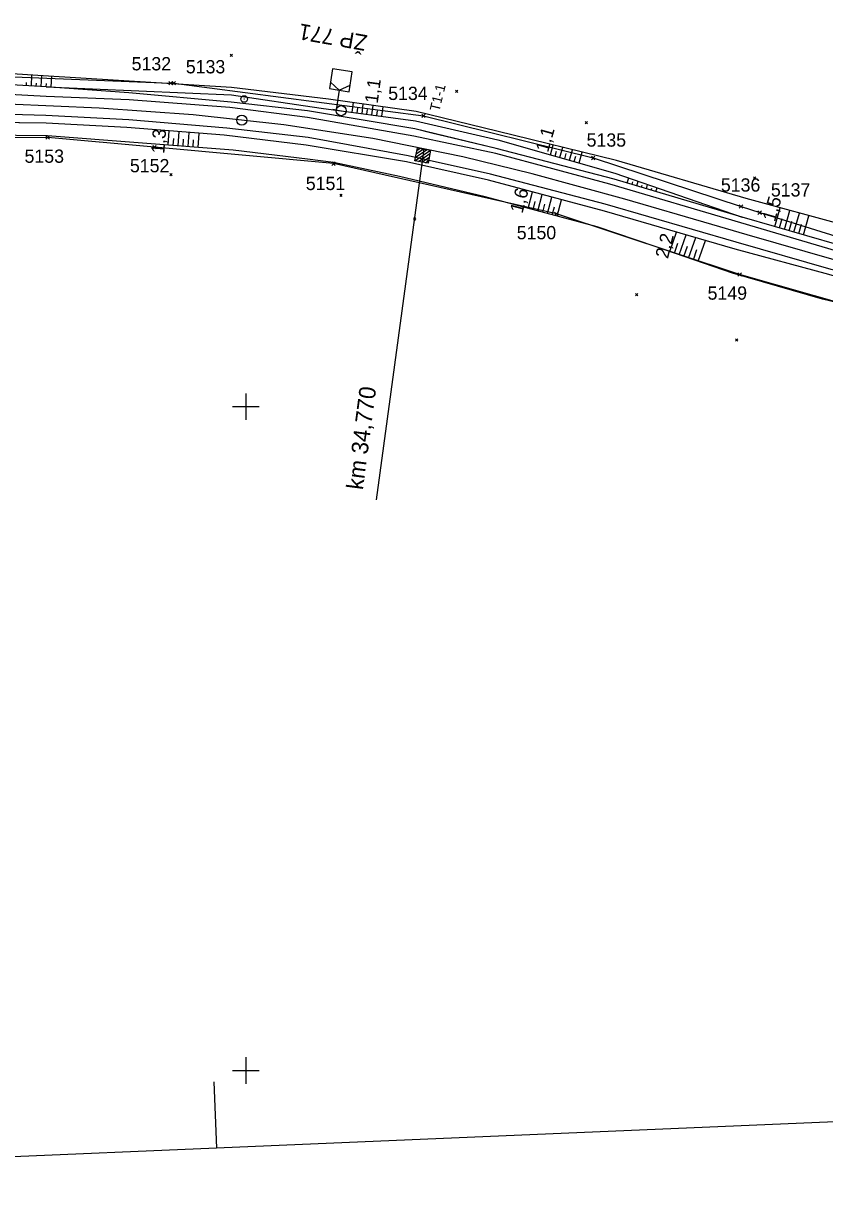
# Model space of a CAD drawing. Extents: x -806456 to -805395, y -1150847 to -1150506.
# Drawn here: x -805633.5 to -805512.8, y -1150820.6 to -1150642.3 of the extents above; entities that cross this region are included whole.
import ezdxf

# ---------------------------------------------------------------- set-up
doc = ezdxf.new("R2010")
doc.units = 0
for name, color, linetype in [('0381KM032-037P - Vrstva 1', 7, 'Continuous'), ('0381KM032-037P - Vrstva 3', 7, 'Continuous'), ('0381KM032-037P - Vrstva 4', 7, 'Continuous'), ('0381KM032-037P - Vrstva 48', 7, 'Continuous'), ('0381KM032-037P - Vrstva 49', 7, 'Continuous'), ('0381KM032-037P - Vrstva 7', 7, 'Continuous'), ('formát', 7, 'Continuous'), ('krizky_1000 - Vrstva 1', 7, 'Continuous'), ('szdc - hran DP', 7, 'Continuous'), ('szdc - szdc_cislo', 7, 'Continuous'), ('szdc - szdc_krizek', 7, 'Continuous'), ('vyt_sit - ohrožené', 7, 'Continuous')]:
    doc.layers.add(name, color=color, linetype=linetype)

msp = doc.modelspace()

# ---------------------------------------------------------------- linework, layer by layer
at = {"layer": '0381KM032-037P - Vrstva 1'}
for points in [[(-805607.93, -1150656.05), (-805622.11, -1150655.05), (-805635.9, -1150654.45), (-805647.61, -1150654.06)], [(-805567.32, -1150662.37), (-805580.89, -1150659.62), (-805594.29, -1150657.54), (-805607.93, -1150656.05)], [(-805529.81, -1150672.54), (-805542.91, -1150668.73), (-805556.85, -1150664.92), (-805567.32, -1150662.37)], [(-805499.4, -1150681.08), (-805511.35, -1150677.89), (-805524.48, -1150674.12), (-805529.81, -1150672.54)]]:
    msp.add_lwpolyline(points, dxfattribs=at)
at = {"layer": '0381KM032-037P - Vrstva 3'}
for p, q in [((-805573.17, -1150661.19), (-805580.37, -1150714.04)), ((-805574.52, -1150662.97), (-805572.18, -1150661.37)), ((-805574.42, -1150662.44), (-805572.71, -1150661.27)), ((-805574.32, -1150661.92), (-805573.23, -1150661.17)), ((-805574.23, -1150661.4), (-805573.75, -1150661.08)), ((-805574, -1150663.06), (-805572.28, -1150661.89)), ((-805573.48, -1150663.16), (-805572.38, -1150662.41)), ((-805572.96, -1150663.26), (-805572.48, -1150662.93))]:
    msp.add_line(p, q, dxfattribs=at)
msp.add_lwpolyline([(-805574.15, -1150661), (-805572.18, -1150661.37), (-805572.55, -1150663.34), (-805574.52, -1150662.97)], close=True, dxfattribs=at)
at = {"layer": '0381KM032-037P - Vrstva 4'}
for points in [[(-805485.85, -1150681.76), (-805498.96, -1150678.92), (-805510.6, -1150675.66), (-805525.22, -1150671.48), (-805544.53, -1150665.72), (-805562.31, -1150661.11), (-805574.56, -1150658.15), (-805590.74, -1150655.42), (-805602.22, -1150654.14), (-805617.62, -1150652.74), (-805630.08, -1150651.83), (-805647.65, -1150650.8), (-805688.26, -1150650.5)], [(-805423.97, -1150686.92), (-805425.51, -1150687.49), (-805433.17, -1150688.49), (-805447.58, -1150687.79), (-805460.54, -1150686.52), (-805473.03, -1150684.97), (-805486, -1150682.53), (-805499.06, -1150679.64), (-805510.93, -1150676.58), (-805525.41, -1150672.29), (-805545.14, -1150666.47), (-805562.36, -1150661.85), (-805574.71, -1150659.28), (-805590.7, -1150656.46), (-805602.42, -1150654.96), (-805617.57, -1150653.8), (-805630.08, -1150653.28), (-805647.6, -1150652.35), (-805687.98, -1150651.47)], [(-805425.98, -1150691.47), (-805433.13, -1150691.22), (-805447.47, -1150690.71), (-805460.74, -1150689.57), (-805473.54, -1150687.87), (-805486.2, -1150685.62), (-805499.7, -1150682.42), (-805511.82, -1150679.35), (-805526.11, -1150675.23), (-805545.84, -1150669.48), (-805563.16, -1150664.96), (-805575.57, -1150662.2), (-805590.62, -1150659.46), (-805602.86, -1150658.06), (-805617.64, -1150656.78), (-805630.16, -1150656.16), (-805647.73, -1150655.65), (-805688.15, -1150654.42)], [(-805425.41, -1150692.47), (-805425.98, -1150691.47), (-805433.11, -1150692.35), (-805447.61, -1150691.82), (-805460.9, -1150690.59), (-805473.67, -1150688.98), (-805486.26, -1150686.57), (-805500.08, -1150683.65), (-805512.15, -1150680.12), (-805526.27, -1150676.26), (-805545.98, -1150670.57), (-805563.42, -1150665.87), (-805575.79, -1150663.12), (-805590.93, -1150660.59), (-805603.28, -1150659.09), (-805617.92, -1150657.97), (-805630.11, -1150657.32), (-805646.66, -1150657.1), (-805648.58, -1150657.2), (-805687.42, -1150655.93)]]:
    msp.add_lwpolyline(points, dxfattribs=at)
at = {"layer": '0381KM032-037P - Vrstva 48'}
for p, q in [((-805633.08, -1150651.65), (-805633.05, -1150651.16)), ((-805632.33, -1150651.7), (-805632.24, -1150650.05)), ((-805631.59, -1150651.74), (-805631.56, -1150651.25)), ((-805630.84, -1150651.79), (-805630.74, -1150650.15)), ((-805630.09, -1150651.83), (-805630.06, -1150651.34)), ((-805629.34, -1150651.86), (-805629.27, -1150650.24)), ((-805583.99, -1150655.65), (-805583.8, -1150654.21)), ((-805583.25, -1150655.75), (-805583.15, -1150655.03)), ((-805582.5, -1150655.85), (-805582.31, -1150654.42)), ((-805581.02, -1150656.05), (-805580.83, -1150654.64)), ((-805579.53, -1150656.25), (-805579.34, -1150654.85)), ((-805581.76, -1150655.95), (-805581.66, -1150655.24)), ((-805580.27, -1150656.15), (-805580.18, -1150655.44)), ((-805611.7, -1150660.6), (-805611.54, -1150658.46)), ((-805610.21, -1150660.72), (-805610.04, -1150658.57)), ((-805610.96, -1150660.66), (-805610.87, -1150659.59)), ((-805609.46, -1150660.78), (-805609.38, -1150659.7)), ((-805608.71, -1150660.83), (-805608.55, -1150658.69)), ((-805607.96, -1150660.89), (-805607.88, -1150659.82)), ((-805607.21, -1150660.95), (-805607.05, -1150658.8)), ((-805554.11, -1150662.05), (-805553.7, -1150660.58)), ((-805553.39, -1150662.26), (-805553.18, -1150661.51)), ((-805552.67, -1150662.46), (-805552.24, -1150660.94)), ((-805551.95, -1150662.67), (-805551.73, -1150661.89)), ((-805551.23, -1150662.87), (-805550.78, -1150661.3)), ((-805549.79, -1150663.28), (-805549.32, -1150661.66)), ((-805550.51, -1150663.08), (-805550.28, -1150662.28)), ((-805542.53, -1150666.31), (-805542.3, -1150665.55)), ((-805541.81, -1150666.53), (-805541.7, -1150666.16)), ((-805541.09, -1150666.74), (-805540.88, -1150666.04)), ((-805540.37, -1150666.96), (-805540.27, -1150666.62)), ((-805539.65, -1150667.17), (-805539.46, -1150666.53)), ((-805538.93, -1150667.39), (-805538.84, -1150667.08)), ((-805538.21, -1150667.6), (-805538.04, -1150667.03)), ((-805557.45, -1150670.15), (-805556.79, -1150667.66)), ((-805556.72, -1150670.35), (-805556.39, -1150669.1)), ((-805556, -1150670.54), (-805555.34, -1150668.05)), ((-805554.55, -1150670.93), (-805553.89, -1150668.44)), ((-805553.1, -1150671.31), (-805552.44, -1150668.83)), ((-805555.28, -1150670.73), (-805554.95, -1150669.49)), ((-805553.83, -1150671.12), (-805553.5, -1150669.88)), ((-805520.31, -1150672.89), (-805519.5, -1150670.07)), ((-805518.86, -1150673.3), (-805518.05, -1150670.46)), ((-805517.42, -1150673.71), (-805516.6, -1150670.86)), ((-805519.58, -1150673.09), (-805519.18, -1150671.68)), ((-805518.14, -1150673.5), (-805517.73, -1150672.08)), ((-805516.7, -1150673.92), (-805516.29, -1150672.49)), ((-805515.98, -1150674.12), (-805515.16, -1150671.25)), ((-805536.11, -1150676.64), (-805535.09, -1150673.71)), ((-805534.69, -1150677.13), (-805533.65, -1150674.13)), ((-805533.28, -1150677.62), (-805532.21, -1150674.54)), ((-805535.4, -1150676.88), (-805534.89, -1150675.4)), ((-805533.99, -1150677.38), (-805533.46, -1150675.85)), ((-805532.57, -1150677.87), (-805532.03, -1150676.31)), ((-805531.86, -1150678.11), (-805530.76, -1150674.96))]:
    msp.add_line(p, q, dxfattribs=at)
at = {"layer": '0381KM032-037P - Vrstva 49'}
for p, q in [((-805602.01, -1150646.92), (-805602.36, -1150647.28)), ((-805602.36, -1150646.92), (-805602.01, -1150647.28)), ((-805568.05, -1150652.69), (-805568.41, -1150652.34)), ((-805568.05, -1150652.34), (-805568.41, -1150652.69)), ((-805548.54, -1150657.39), (-805548.89, -1150657.04)), ((-805548.54, -1150657.04), (-805548.89, -1150657.39)), ((-805611.13, -1150664.88), (-805611.48, -1150665.23)), ((-805611.48, -1150664.88), (-805611.12, -1150665.23)), ((-805523.18, -1150665.72), (-805523.53, -1150665.37)), ((-805523.18, -1150665.37), (-805523.53, -1150665.72)), ((-805585.52, -1150668), (-805585.87, -1150668.36)), ((-805585.87, -1150668), (-805585.52, -1150668.36)), ((-805574.41, -1150671.9), (-805574.76, -1150671.55)), ((-805574.41, -1150671.55), (-805574.76, -1150671.9)), ((-805540.92, -1150683.33), (-805541.28, -1150682.98)), ((-805540.92, -1150682.98), (-805541.28, -1150683.33)), ((-805525.86, -1150690.16), (-805526.21, -1150689.81)), ((-805525.86, -1150689.81), (-805526.21, -1150690.16))]:
    msp.add_line(p, q, dxfattribs=at)
for points in [[(-805602.19, -1150651.94), (-805630.54, -1150650.16), (-805647.04, -1150649.14), (-805681.66, -1150649.9), (-805688.26, -1150650.5)], [(-805423.97, -1150686.92), (-805433.1, -1150687.91), (-805447.34, -1150686.91), (-805460.49, -1150686.09), (-805485.85, -1150681.76), (-805498.96, -1150678.92), (-805510.6, -1150675.66), (-805525.22, -1150671.48), (-805544.53, -1150665.72), (-805562.31, -1150661.11), (-805571.99, -1150658.79), (-805574.56, -1150658.15), (-805590.74, -1150655.42), (-805602.22, -1150654.14), (-805617.62, -1150652.74), (-805630.08, -1150651.83), (-805647.65, -1150650.8), (-805688.26, -1150650.5)], [(-805630.08, -1150651.83), (-805602.16, -1150653.02), (-805588.68, -1150655.02)], [(-805424.36, -1150683.57), (-805432.74, -1150683.28), (-805452.35, -1150683.91), (-805462.43, -1150682.34), (-805472.3, -1150680.9), (-805485.84, -1150678.15), (-805509.51, -1150672.79), (-805524.62, -1150668.67), (-805544.15, -1150662.92), (-805562.19, -1150658.51), (-805574.34, -1150655.56), (-805587.56, -1150653.68), (-805602.19, -1150651.94)], [(-805588.68, -1150655.02), (-805574.43, -1150656.93), (-805562.03, -1150659.8), (-805544.41, -1150664.81), (-805525.22, -1150671.48)], [(-805425.41, -1150692.47), (-805425.98, -1150691.47), (-805433.11, -1150692.35), (-805447.61, -1150691.82), (-805460.9, -1150690.59), (-805473.67, -1150688.98), (-805486.26, -1150686.57), (-805500.08, -1150683.65), (-805512.15, -1150680.12), (-805526.27, -1150676.26), (-805545.98, -1150670.57), (-805563.42, -1150665.87), (-805575.79, -1150663.12), (-805590.93, -1150660.59), (-805603.28, -1150659.09), (-805617.92, -1150657.97), (-805630.11, -1150657.32), (-805646.15, -1150657.11), (-805646.27, -1150657.1), (-805646.57, -1150657.13), (-805646.66, -1150657.1), (-805648.58, -1150657.2), (-805687.42, -1150655.93)], [(-805428.8, -1150698.61), (-805426.99, -1150695.45), (-805434.79, -1150695.76), (-805452.59, -1150694.8), (-805474.79, -1150691.73), (-805486.9, -1150690.07), (-805513.13, -1150683.83), (-805526.69, -1150679.91), (-805538.18, -1150675.92), (-805547.05, -1150672.92), (-805563.97, -1150668.42), (-805576.87, -1150665.35), (-805586.81, -1150663.24), (-805590.73, -1150662.74), (-805601.92, -1150661.35), (-805629.88, -1150659.22), (-805648.74, -1150658.99), (-805687.58, -1150660.02)]]:
    msp.add_lwpolyline(points, dxfattribs=at)
at = {"layer": '0381KM032-037P - Vrstva 7'}
for p, q in [((-805585.93, -1150652.33), (-805586.39, -1150655.29)), ((-805600.32, -1150653.66), (-805600.22, -1150653.66)), ((-805586.89, -1150655.21), (-805585.9, -1150655.37))]:
    msp.add_line(p, q, dxfattribs=at)
for points in [[(-805585.93, -1150652.33), (-805584.45, -1150652.56), (-805583.99, -1150649.59), (-805586.96, -1150649.13), (-805587.42, -1150652.1), (-805585.93, -1150652.33)], [(-805587.26, -1150651.11), (-805585.93, -1150652.33), (-805584.3, -1150651.57)]]:
    msp.add_lwpolyline(points, dxfattribs=at)
for centre, radius in [((-805600.27, -1150653.66), 0.5), ((-805600.62, -1150656.85), 0.75)]:
    msp.add_circle(centre, radius, dxfattribs=at)
at = {"layer": 'formát'}
for p, q in [((-805604.84, -1150801.71), (-805604.42, -1150811.7)), ((-805394.61, -1150802.8), (-805604.42, -1150811.7)), ((-805604.42, -1150811.7), (-805814.23, -1150820.61))]:
    msp.add_line(p, q, dxfattribs=at)
at = {"layer": 'krizky_1000 - Vrstva 1'}
for points in [[(-805600, -1150698), (-805600, -1150702)], [(-805602, -1150700), (-805598, -1150700)], [(-805600, -1150798), (-805600, -1150802)], [(-805602, -1150800), (-805598, -1150800)]]:
    msp.add_lwpolyline(points, dxfattribs=at)
at = {"layer": 'szdc - hran DP'}
for p, q in [((-805645.21, -1150649.93), (-805611.34, -1150651.29)), ((-805611.34, -1150651.29), (-805610.86, -1150651.29)), ((-805610.86, -1150651.29), (-805573.24, -1150656.2)), ((-805573.24, -1150656.2), (-805547.66, -1150662.54)), ((-805629.87, -1150659.45), (-805660.75, -1150659.79)), ((-805613.77, -1150660.92), (-805629.87, -1150659.45)), ((-805586.79, -1150663.39), (-805613.77, -1150660.92)), ((-805553.22, -1150670.95), (-805586.79, -1150663.39)), ((-805547.66, -1150662.54), (-805525.39, -1150669.85)), ((-805525.6, -1150680.1), (-805553.22, -1150670.95)), ((-805525.39, -1150669.85), (-805522.57, -1150670.78)), ((-805522.57, -1150670.78), (-805505.56, -1150676.07)), ((-805492.06, -1150689.65), (-805525.6, -1150680.1))]:
    msp.add_line(p, q, dxfattribs=at)
at = {"layer": 'szdc - szdc_krizek'}
for p, q in [((-805611.08, -1150651.55), (-805611.61, -1150651.03)), ((-805611.61, -1150651.55), (-805611.08, -1150651.03)), ((-805610.59, -1150651.55), (-805611.13, -1150651.03)), ((-805611.13, -1150651.55), (-805610.59, -1150651.03)), ((-805572.97, -1150656.47), (-805573.51, -1150655.94)), ((-805573.51, -1150656.47), (-805572.97, -1150655.94)), ((-805629.6, -1150659.72), (-805630.14, -1150659.19)), ((-805630.14, -1150659.72), (-805629.6, -1150659.19)), ((-805613.51, -1150661.19), (-805614.04, -1150660.66)), ((-805614.04, -1150661.19), (-805613.51, -1150660.66)), ((-805586.53, -1150663.66), (-805587.06, -1150663.12)), ((-805587.06, -1150663.66), (-805586.53, -1150663.12)), ((-805547.4, -1150662.8), (-805547.93, -1150662.28)), ((-805547.93, -1150662.8), (-805547.4, -1150662.28)), ((-805552.96, -1150671.22), (-805553.49, -1150670.69)), ((-805553.49, -1150671.22), (-805552.96, -1150670.69)), ((-805525.12, -1150670.11), (-805525.66, -1150669.58)), ((-805525.66, -1150670.11), (-805525.12, -1150669.58)), ((-805522.31, -1150671.04), (-805522.84, -1150670.52)), ((-805522.84, -1150671.04), (-805522.31, -1150670.52)), ((-805525.33, -1150680.36), (-805525.87, -1150679.83)), ((-805525.87, -1150680.36), (-805525.33, -1150679.83))]:
    msp.add_line(p, q, dxfattribs=at)
at = {"layer": 'vyt_sit - ohrožené'}
msp.add_line((-805585.69, -1150655.42), (-805585.58, -1150655.42), dxfattribs=at)
msp.add_circle((-805585.64, -1150655.42), 0.756, dxfattribs=at)

# ---------------------------------------------------------------- texts
at = {"layer": '0381KM032-037P - Vrstva 3'}
for s, height, rotation, p in [('T1-1', 1.5, 76.1469, (-805570.87, -1150655.63)), ('km 34,770', 2.5, 82.5204, (-805582.38, -1150712.62))]:
    msp.add_text(s, height=height, rotation=rotation, dxfattribs=at).set_placement(p)
at = {"layer": '0381KM032-037P - Vrstva 48'}
for s, rotation, p in [('1,1', 82.3827, (-805580.14, -1150654.4)), ('1,3', 85.6488, (-805612.3, -1150661.94)), ('1,1', 74.1019, (-805554.47, -1150661.8)), ('1,6', 75.1245, (-805558.33, -1150670.98)), ('1,5', 74.0489, (-805520.28, -1150672.25)), ('2,2', 75.6961, (-805536.41, -1150677.81))]:
    msp.add_text(s, height=2, rotation=rotation, dxfattribs=at).set_placement(p)
at = {"layer": 'szdc - szdc_cislo'}
for s, p in [('5132', (-805617.22, -1150649.35)), ('5133', (-805609.06, -1150649.8)), ('5134', (-805578.56, -1150653.81)), ('5135', (-805548.66, -1150660.84)), ('5153', (-805633.36, -1150663.27)), ('5152', (-805617.48, -1150664.7)), ('5151', (-805590.98, -1150667.38)), ('5136', (-805528.43, -1150667.61)), ('5137', (-805520.89, -1150668.35)), ('5150', (-805559.19, -1150674.79)), ('5149', (-805530.43, -1150683.89))]:
    msp.add_text(s, height=2, dxfattribs=at).set_placement(p)
at = {"layer": 'vyt_sit - ohrožené'}
msp.add_text('ŽP 771', height=2.4, rotation=170, dxfattribs=at).set_placement((-805581.59, -1150644.08))

doc.saveas('drawing.dxf')
